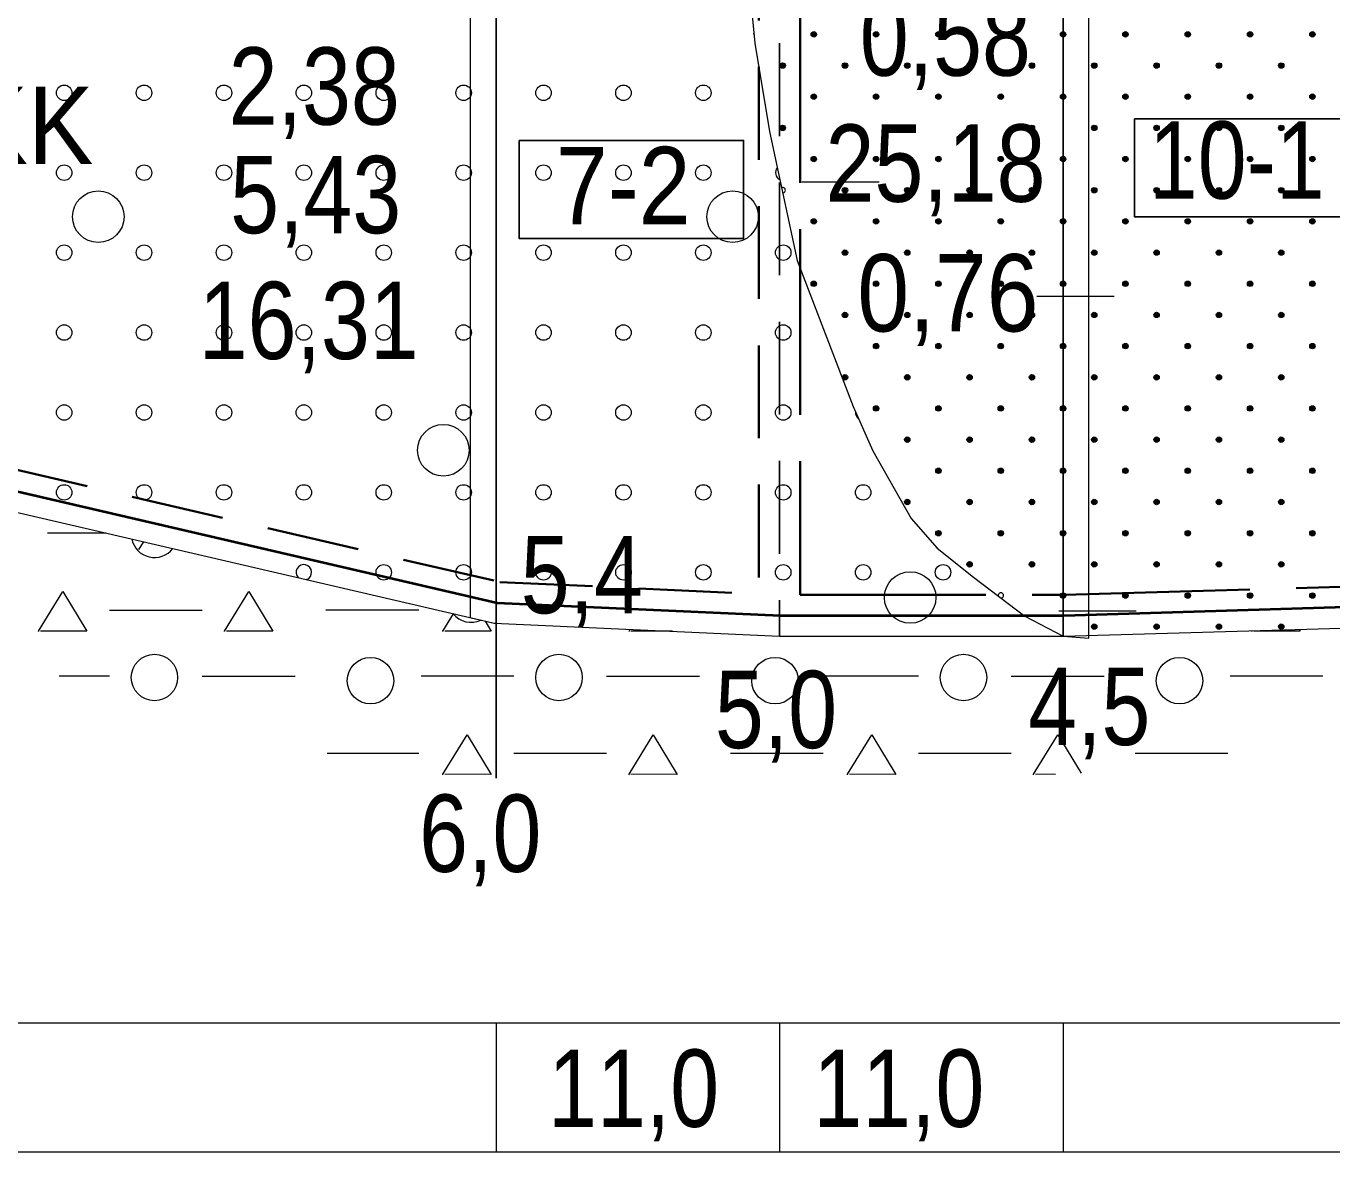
# Model space of a CAD drawing. Extents: x 640104 to 640970, y 6442278 to 6442689.
# Drawn here: x 640855 to 640905.7, y 6442488.9 to 6442532.6 of the extents above; entities that cross this region are included whole.
import ezdxf
from ezdxf.enums import TextEntityAlignment as Align

# ---------------------------------------------------------------- set-up
doc = ezdxf.new("R2010")
doc.units = 0
doc.header["$LTSCALE"] = 1.2
doc.linetypes.add('LONG_DASHED', pattern=[7.5, 6, -1.5])
doc.linetypes.add('MEDIUM_DASHED', pattern=[4.5, 3, -1.5])
for name, color, linetype, lineweight in [('30', 7, 'Continuous', 13), ('31', 7, 'Continuous', 13), ('32', 7, 'Continuous', 25), ('33', 7, 'Continuous', 13), ('35', 7, 'Continuous', 35), ('43', 7, 'Continuous', 13), ('45', 7, 'Continuous', 13), ('46', 7, 'Continuous', 13), ('47', 7, 'Continuous', 13)]:
    doc.layers.add(name, color=color, linetype=linetype, lineweight=lineweight)

msp = doc.modelspace()

# ---------------------------------------------------------------- hatches: boundary and pattern name
at = {"layer": '45'}
for points in [[(640885.671, 6442532.358, 1), (640885.523, 6442532.21, 1)], [(640888.089, 6442532.358, 1), (640887.941, 6442532.21, 1)], [(640890.508, 6442532.358, 1), (640890.359, 6442532.21, 1)], [(640892.926, 6442532.358, 1), (640892.777, 6442532.21, 1)], [(640895.344, 6442532.358, 1), (640895.196, 6442532.21, 1)], [(640897.763, 6442532.358, 1), (640897.614, 6442532.21, 1)], [(640900.181, 6442532.358, 1), (640900.032, 6442532.21, 1)], [(640902.599, 6442532.358, 1), (640902.451, 6442532.21, 1)], [(640905.017, 6442532.358, 1), (640904.869, 6442532.21, 1)], [(640884.462, 6442531.149, 1), (640884.313, 6442531, 1)], [(640886.88, 6442531.149, 1), (640886.732, 6442531, 1)], [(640889.299, 6442531.149, 1), (640889.15, 6442531, 1)], [(640891.717, 6442531.149, 1), (640891.568, 6442531, 1)], [(640894.135, 6442531.149, 1), (640893.987, 6442531, 1)], [(640896.553, 6442531.149, 1), (640896.405, 6442531, 1)], [(640898.972, 6442531.149, 1), (640898.823, 6442531, 1)], [(640901.39, 6442531.149, 1), (640901.242, 6442531, 1)], [(640903.808, 6442531.149, 1), (640903.66, 6442531, 1)], [(640885.671, 6442529.94, 1), (640885.523, 6442529.791, 1)], [(640888.089, 6442529.94, 1), (640887.941, 6442529.791, 1)], [(640890.508, 6442529.94, 1), (640890.359, 6442529.791, 1)], [(640892.926, 6442529.94, 1), (640892.777, 6442529.791, 1)], [(640895.344, 6442529.94, 1), (640895.196, 6442529.791, 1)], [(640897.763, 6442529.94, 1), (640897.614, 6442529.791, 1)], [(640900.181, 6442529.94, 1), (640900.032, 6442529.791, 1)], [(640902.599, 6442529.94, 1), (640902.451, 6442529.791, 1)], [(640905.017, 6442529.94, 1), (640904.869, 6442529.791, 1)], [(640884.462, 6442528.731, 1), (640884.313, 6442528.582, 1)], [(640886.88, 6442528.731, 1), (640886.732, 6442528.582, 1)], [(640889.299, 6442528.731, 1), (640889.15, 6442528.582, 1)], [(640891.717, 6442528.731, 1), (640891.568, 6442528.582, 1)], [(640894.135, 6442528.731, 1), (640893.987, 6442528.582, 1)], [(640896.553, 6442528.731, 1), (640896.405, 6442528.582, 1)], [(640898.972, 6442528.731, 1), (640898.823, 6442528.582, 1)], [(640901.39, 6442528.731, 1), (640901.242, 6442528.582, 1)], [(640903.808, 6442528.731, 1), (640903.66, 6442528.582, 1)], [(640885.671, 6442527.522, 1), (640885.523, 6442527.373, 1)], [(640888.089, 6442527.522, 1), (640887.941, 6442527.373, 1)], [(640890.508, 6442527.522, 1), (640890.359, 6442527.373, 1)], [(640892.926, 6442527.522, 1), (640892.777, 6442527.373, 1)], [(640895.344, 6442527.522, 1), (640895.196, 6442527.373, 1)], [(640897.763, 6442527.522, 1), (640897.614, 6442527.373, 1)], [(640900.181, 6442527.522, 1), (640900.032, 6442527.373, 1)], [(640902.599, 6442527.522, 1), (640902.451, 6442527.373, 1)], [(640905.017, 6442527.522, 1), (640904.869, 6442527.373, 1)], [(640886.88, 6442526.312, 1), (640886.732, 6442526.164, 1)], [(640889.299, 6442526.312, 1), (640889.15, 6442526.164, 1)], [(640891.717, 6442526.312, 1), (640891.568, 6442526.164, 1)], [(640894.135, 6442526.312, 1), (640893.987, 6442526.164, 1)], [(640896.553, 6442526.312, 1), (640896.405, 6442526.164, 1)], [(640898.972, 6442526.312, 1), (640898.823, 6442526.164, 1)], [(640901.39, 6442526.312, 1), (640901.242, 6442526.164, 1)], [(640903.808, 6442526.312, 1), (640903.66, 6442526.164, 1)], [(640885.671, 6442525.103, 1), (640885.523, 6442524.955, 1)], [(640888.089, 6442525.103, 1), (640887.941, 6442524.955, 1)], [(640890.508, 6442525.103, 1), (640890.359, 6442524.955, 1)], [(640892.926, 6442525.103, 1), (640892.777, 6442524.955, 1)], [(640895.344, 6442525.103, 1), (640895.196, 6442524.955, 1)], [(640897.763, 6442525.103, 1), (640897.614, 6442524.955, 1)], [(640900.181, 6442525.103, 1), (640900.032, 6442524.955, 1)], [(640902.599, 6442525.103, 1), (640902.451, 6442524.955, 1)], [(640905.017, 6442525.103, 1), (640904.869, 6442524.955, 1)], [(640886.88, 6442523.894, 1), (640886.732, 6442523.746, 1)], [(640889.299, 6442523.894, 1), (640889.15, 6442523.746, 1)], [(640891.717, 6442523.894, 1), (640891.568, 6442523.746, 1)], [(640894.135, 6442523.894, 1), (640893.987, 6442523.746, 1)], [(640896.553, 6442523.894, 1), (640896.405, 6442523.746, 1)], [(640898.972, 6442523.894, 1), (640898.823, 6442523.746, 1)], [(640901.39, 6442523.894, 1), (640901.242, 6442523.746, 1)], [(640903.808, 6442523.894, 1), (640903.66, 6442523.746, 1)], [(640885.671, 6442522.685, 1), (640885.523, 6442522.536, 1)], [(640888.089, 6442522.685, 1), (640887.941, 6442522.536, 1)], [(640890.508, 6442522.685, 1), (640890.359, 6442522.536, 1)], [(640892.926, 6442522.685, 1), (640892.777, 6442522.536, 1)], [(640895.344, 6442522.685, 1), (640895.196, 6442522.536, 1)], [(640897.763, 6442522.685, 1), (640897.614, 6442522.536, 1)], [(640900.181, 6442522.685, 1), (640900.032, 6442522.536, 1)], [(640902.599, 6442522.685, 1), (640902.451, 6442522.536, 1)], [(640905.017, 6442522.685, 1), (640904.869, 6442522.536, 1)], [(640886.88, 6442521.476, 1), (640886.732, 6442521.327, 1)], [(640889.299, 6442521.476, 1), (640889.15, 6442521.327, 1)], [(640891.717, 6442521.476, 1), (640891.568, 6442521.327, 1)], [(640894.135, 6442521.476, 1), (640893.987, 6442521.327, 1)], [(640896.553, 6442521.476, 1), (640896.405, 6442521.327, 1)], [(640898.972, 6442521.476, 1), (640898.823, 6442521.327, 1)], [(640901.39, 6442521.476, 1), (640901.242, 6442521.327, 1)], [(640903.808, 6442521.476, 1), (640903.66, 6442521.327, 1)], [(640888.089, 6442520.267, 1), (640887.941, 6442520.118, 1)], [(640890.508, 6442520.267, 1), (640890.359, 6442520.118, 1)], [(640892.926, 6442520.267, 1), (640892.777, 6442520.118, 1)], [(640895.344, 6442520.267, 1), (640895.196, 6442520.118, 1)], [(640897.763, 6442520.267, 1), (640897.614, 6442520.118, 1)], [(640900.181, 6442520.267, 1), (640900.032, 6442520.118, 1)], [(640902.599, 6442520.267, 1), (640902.451, 6442520.118, 1)], [(640905.017, 6442520.267, 1), (640904.869, 6442520.118, 1)], [(640886.88, 6442519.057, 1), (640886.732, 6442518.909, 1)], [(640889.299, 6442519.057, 1), (640889.15, 6442518.909, 1)], [(640891.717, 6442519.057, 1), (640891.568, 6442518.909, 1)], [(640894.135, 6442519.057, 1), (640893.987, 6442518.909, 1)], [(640896.553, 6442519.057, 1), (640896.405, 6442518.909, 1)], [(640898.972, 6442519.057, 1), (640898.823, 6442518.909, 1)], [(640901.39, 6442519.057, 1), (640901.242, 6442518.909, 1)], [(640903.808, 6442519.057, 1), (640903.66, 6442518.909, 1)], [(640888.089, 6442517.848, 1), (640887.941, 6442517.7, 1)], [(640890.508, 6442517.848, 1), (640890.359, 6442517.7, 1)], [(640892.926, 6442517.848, 1), (640892.777, 6442517.7, 1)], [(640895.344, 6442517.848, 1), (640895.196, 6442517.7, 1)], [(640897.763, 6442517.848, 1), (640897.614, 6442517.7, 1)], [(640900.181, 6442517.848, 1), (640900.032, 6442517.7, 1)], [(640902.599, 6442517.848, 1), (640902.451, 6442517.7, 1)], [(640905.017, 6442517.848, 1), (640904.869, 6442517.7, 1)], [(640889.299, 6442516.639, 1), (640889.15, 6442516.491, 1)], [(640891.717, 6442516.639, 1), (640891.568, 6442516.491, 1)], [(640894.135, 6442516.639, 1), (640893.987, 6442516.491, 1)], [(640896.553, 6442516.639, 1), (640896.405, 6442516.491, 1)], [(640898.972, 6442516.639, 1), (640898.823, 6442516.491, 1)], [(640901.39, 6442516.639, 1), (640901.242, 6442516.491, 1)], [(640903.808, 6442516.639, 1), (640903.66, 6442516.491, 1)], [(640890.508, 6442515.43, 1), (640890.359, 6442515.282, 1)], [(640892.926, 6442515.43, 1), (640892.777, 6442515.282, 1)], [(640895.344, 6442515.43, 1), (640895.196, 6442515.282, 1)], [(640897.763, 6442515.43, 1), (640897.614, 6442515.282, 1)], [(640900.181, 6442515.43, 1), (640900.032, 6442515.282, 1)], [(640902.599, 6442515.43, 1), (640902.451, 6442515.282, 1)], [(640905.017, 6442515.43, 1), (640904.869, 6442515.282, 1)], [(640889.299, 6442514.221, 1), (640889.15, 6442514.072, 1)], [(640891.717, 6442514.221, 1), (640891.568, 6442514.072, 1)], [(640894.135, 6442514.221, 1), (640893.987, 6442514.072, 1)], [(640896.553, 6442514.221, 1), (640896.405, 6442514.072, 1)], [(640898.972, 6442514.221, 1), (640898.823, 6442514.072, 1)], [(640901.39, 6442514.221, 1), (640901.242, 6442514.072, 1)], [(640903.808, 6442514.221, 1), (640903.66, 6442514.072, 1)], [(640890.508, 6442513.012, 1), (640890.359, 6442512.863, 1)], [(640892.926, 6442513.012, 1), (640892.777, 6442512.863, 1)], [(640895.344, 6442513.012, 1), (640895.196, 6442512.863, 1)], [(640897.763, 6442513.012, 1), (640897.614, 6442512.863, 1)], [(640900.181, 6442513.012, 1), (640900.032, 6442512.863, 1)], [(640902.599, 6442513.012, 1), (640902.451, 6442512.863, 1)], [(640905.017, 6442513.012, 1), (640904.869, 6442512.863, 1)], [(640891.717, 6442511.803, 1), (640891.568, 6442511.654, 1)], [(640894.135, 6442511.803, 1), (640893.987, 6442511.654, 1)], [(640896.553, 6442511.803, 1), (640896.405, 6442511.654, 1)], [(640898.972, 6442511.803, 1), (640898.823, 6442511.654, 1)], [(640901.39, 6442511.803, 1), (640901.242, 6442511.654, 1)], [(640903.808, 6442511.803, 1), (640903.66, 6442511.654, 1)], [(640895.344, 6442510.593, 1), (640895.196, 6442510.445, 1)], [(640897.763, 6442510.593, 1), (640897.614, 6442510.445, 1)], [(640900.181, 6442510.593, 1), (640900.032, 6442510.445, 1)], [(640902.599, 6442510.593, 1), (640902.451, 6442510.445, 1)], [(640905.017, 6442510.593, 1), (640904.869, 6442510.445, 1)], [(640896.553, 6442509.384, 1), (640896.405, 6442509.236, 1)], [(640898.972, 6442509.384, 1), (640898.823, 6442509.236, 1)], [(640901.39, 6442509.384, 1), (640901.242, 6442509.236, 1)], [(640903.808, 6442509.384, 1), (640903.66, 6442509.236, 1)]]:
    msp.add_hatch(color=256, dxfattribs=at).paths.add_polyline_path(points)

# ---------------------------------------------------------------- linework, layer by layer
at = {"layer": '30'}
for p, q in [((640524.54, 6442493.94), (640955.05, 6442493.94)), ((640873.27, 6442493.94), (640873.27, 6442488.94)), ((640884.27, 6442493.94), (640884.27, 6442488.94)), ((640895.27, 6442493.94), (640895.27, 6442488.94)), ((640524.54, 6442488.94), (640955.05, 6442488.94))]:
    msp.add_line(p, q, dxfattribs=at)
at = {"layer": '31'}
for points in [[(640553.71, 6442558.56), (640570.07, 6442558.94), (640649.85, 6442563.98), (640763.79, 6442536.22), (640808.67, 6442524.48), (640822.17, 6442520.94), (640837.77, 6442517.67), (640873.2, 6442509.45), (640884.27, 6442508.94), (640895.27, 6442508.94), (640947.47, 6442510.44), (640955.05, 6442510.44)], [(640879.76, 6442556.13), (640880.17, 6442555.04), (640880.81, 6442552.82), (640881.98, 6442546.26), (640882.74, 6442537.89), (640883.31, 6442531.94), (640883.88, 6442528.51), (640884.95, 6442523.51), (640887.12, 6442517.85), (640887.89, 6442516.13), (640889.37, 6442513.51), (640890.38, 6442512.35), (640891.79, 6442511.23), (640893.79, 6442509.72), (640895.27, 6442508.94)]]:
    msp.add_lwpolyline(points, dxfattribs=at)
at = {"layer": '32'}
for p, q in [((640873.27, 6442563.44), (640873.27, 6442503.44)), ((640895.27, 6442553.94), (640895.27, 6442508.94))]:
    msp.add_line(p, q, dxfattribs=at)
at = {"layer": '32', "linetype": 'MEDIUM_DASHED'}
msp.add_line((640884.27, 6442558.94), (640884.27, 6442508.94), dxfattribs=at)
at = {"layer": '33'}
for points in [[(640896.27, 6442548.59), (640895.37, 6442548.86), (640895.27, 6442548.86), (640895.27, 6442508.94), (640896.27, 6442508.87), (640896.27, 6442508.94)], [(640872.27, 6442538.44), (640872.27, 6442509.66), (640873.2, 6442509.45), (640873.27, 6442509.45), (640873.27, 6442538.44)]]:
    msp.add_lwpolyline(points, close=True, dxfattribs=at)
at = {"layer": '33', "lineweight": 25}
for points in [[(640898.04, 6442529.01), (640906.75, 6442529.01), (640906.75, 6442525.21), (640898.04, 6442525.21)], [(640874.16, 6442528.17), (640882.87, 6442528.17), (640882.87, 6442524.37), (640874.16, 6442524.37)]]:
    msp.add_lwpolyline(points, close=True, dxfattribs=at)
at = {"layer": '35', "linetype": 'LONG_DASHED'}
msp.add_line((640885.07, 6442551.73), (640885.07, 6442510.54), dxfattribs=at)
at = {"layer": '35', "linetype": 'MEDIUM_DASHED'}
msp.add_line((640883.47, 6442536.42), (640883.47, 6442510.58), dxfattribs=at)
msp.add_lwpolyline([(640823.77, 6442522.24), (640838.11, 6442519.23), (640873.42, 6442511.04), (640883.47, 6442510.58)], dxfattribs=at)
at = {"layer": '35', "lineweight": 40}
msp.add_lwpolyline([(640822.97, 6442521.59), (640837.94, 6442518.45), (640873.31, 6442510.24), (640884.29, 6442509.74), (640895.3, 6442509.74), (640946.67, 6442511.32)], dxfattribs=at)
at = {"layer": '35', "linetype": 'LONG_DASHED'}
msp.add_lwpolyline([(640885.07, 6442510.54), (640895.32, 6442510.54), (640945.87, 6442512.06)], dxfattribs=at)
at = {"layer": '43'}
for centre in [(640856.511, 6442530.018), (640859.611, 6442530.018), (640862.711, 6442530.018), (640865.811, 6442530.018), (640868.911, 6442530.018), (640872.011, 6442530.018), (640875.111, 6442530.018), (640878.211, 6442530.018), (640881.311, 6442530.018), (640856.511, 6442526.918), (640859.611, 6442526.918), (640862.711, 6442526.918), (640865.811, 6442526.918), (640868.911, 6442526.918), (640872.011, 6442526.918), (640875.111, 6442526.918), (640878.211, 6442526.918), (640881.311, 6442526.918), (640856.511, 6442523.818), (640859.611, 6442523.818), (640862.711, 6442523.818), (640865.811, 6442523.818), (640868.911, 6442523.818), (640872.011, 6442523.818), (640875.111, 6442523.818), (640878.211, 6442523.818), (640881.311, 6442523.818), (640884.411, 6442523.818), (640856.511, 6442520.718), (640859.611, 6442520.718), (640862.711, 6442520.718), (640865.811, 6442520.718), (640868.911, 6442520.718), (640872.011, 6442520.718), (640875.111, 6442520.718), (640878.211, 6442520.718), (640881.311, 6442520.718), (640884.411, 6442520.718), (640856.511, 6442517.618), (640859.611, 6442517.618), (640862.711, 6442517.618), (640865.811, 6442517.618), (640868.911, 6442517.618), (640872.011, 6442517.618), (640875.111, 6442517.618), (640878.211, 6442517.618), (640881.311, 6442517.618), (640884.411, 6442517.618), (640856.511, 6442514.518), (640859.611, 6442514.518), (640862.711, 6442514.518), (640865.811, 6442514.518), (640868.911, 6442514.518), (640872.011, 6442514.518), (640875.111, 6442514.518), (640878.211, 6442514.518), (640881.311, 6442514.518), (640884.411, 6442514.518), (640887.511, 6442514.518), (640868.911, 6442511.418), (640872.011, 6442511.418), (640875.111, 6442511.418), (640878.211, 6442511.418), (640881.311, 6442511.418), (640884.411, 6442511.418), (640887.511, 6442511.418), (640890.611, 6442511.418)]:
    msp.add_circle(centre, 0.3, dxfattribs=at)
for centre, start, end in [((640884.411, 6442526.918), 140.7659, 243.5192), ((640887.511, 6442517.618), 173.8824, 234.2968), ((640865.811, 6442511.418), 290.4586, 223.403)]:
    msp.add_arc(centre, 0.3, start, end, dxfattribs=at)
at = {"layer": '45'}
for centre in [(640885.597, 6442532.284), (640888.015, 6442532.284), (640890.433, 6442532.284), (640892.852, 6442532.284), (640895.27, 6442532.284), (640897.688, 6442532.284), (640900.107, 6442532.284), (640902.525, 6442532.284), (640904.943, 6442532.284), (640884.388, 6442531.075), (640886.806, 6442531.075), (640889.224, 6442531.075), (640891.643, 6442531.075), (640894.061, 6442531.075), (640896.479, 6442531.075), (640898.897, 6442531.075), (640901.316, 6442531.075), (640903.734, 6442531.075), (640885.597, 6442529.866), (640888.015, 6442529.866), (640890.433, 6442529.866), (640892.852, 6442529.866), (640895.27, 6442529.866), (640897.688, 6442529.866), (640900.107, 6442529.866), (640902.525, 6442529.866), (640904.943, 6442529.866), (640884.388, 6442528.656), (640886.806, 6442528.656), (640889.224, 6442528.656), (640891.643, 6442528.656), (640894.061, 6442528.656), (640896.479, 6442528.656), (640898.897, 6442528.656), (640901.316, 6442528.656), (640903.734, 6442528.656), (640885.597, 6442527.447), (640888.015, 6442527.447), (640890.433, 6442527.447), (640892.852, 6442527.447), (640895.27, 6442527.447), (640897.688, 6442527.447), (640900.107, 6442527.447), (640902.525, 6442527.447), (640904.943, 6442527.447), (640886.806, 6442526.238), (640889.224, 6442526.238), (640891.643, 6442526.238), (640894.061, 6442526.238), (640896.479, 6442526.238), (640898.897, 6442526.238), (640901.316, 6442526.238), (640903.734, 6442526.238), (640885.597, 6442525.029), (640888.015, 6442525.029), (640890.433, 6442525.029), (640892.852, 6442525.029), (640895.27, 6442525.029), (640897.688, 6442525.029), (640900.107, 6442525.029), (640902.525, 6442525.029), (640904.943, 6442525.029), (640886.806, 6442523.82), (640889.224, 6442523.82), (640891.643, 6442523.82), (640894.061, 6442523.82), (640896.479, 6442523.82), (640898.897, 6442523.82), (640901.316, 6442523.82), (640903.734, 6442523.82), (640885.597, 6442522.611), (640888.015, 6442522.611), (640890.433, 6442522.611), (640892.852, 6442522.611), (640895.27, 6442522.611), (640897.688, 6442522.611), (640900.107, 6442522.611), (640902.525, 6442522.611), (640904.943, 6442522.611), (640886.806, 6442521.402), (640889.224, 6442521.402), (640891.643, 6442521.402), (640894.061, 6442521.402), (640896.479, 6442521.402), (640898.897, 6442521.402), (640901.316, 6442521.402), (640903.734, 6442521.402), (640888.015, 6442520.192), (640890.433, 6442520.192), (640892.852, 6442520.192), (640895.27, 6442520.192), (640897.688, 6442520.192), (640900.107, 6442520.192), (640902.525, 6442520.192), (640904.943, 6442520.192), (640886.806, 6442518.983), (640889.224, 6442518.983), (640891.643, 6442518.983), (640894.061, 6442518.983), (640896.479, 6442518.983), (640898.897, 6442518.983), (640901.316, 6442518.983), (640903.734, 6442518.983), (640888.015, 6442517.774), (640890.433, 6442517.774), (640892.852, 6442517.774), (640895.27, 6442517.774), (640897.688, 6442517.774), (640900.107, 6442517.774), (640902.525, 6442517.774), (640904.943, 6442517.774), (640889.224, 6442516.565), (640891.643, 6442516.565), (640894.061, 6442516.565), (640896.479, 6442516.565), (640898.897, 6442516.565), (640901.316, 6442516.565), (640903.734, 6442516.565), (640890.433, 6442515.356), (640892.852, 6442515.356), (640895.27, 6442515.356), (640897.688, 6442515.356), (640900.107, 6442515.356), (640902.525, 6442515.356), (640904.943, 6442515.356), (640889.224, 6442514.147), (640891.643, 6442514.147), (640894.061, 6442514.147), (640896.479, 6442514.147), (640898.897, 6442514.147), (640901.316, 6442514.147), (640903.734, 6442514.147), (640890.433, 6442512.937), (640892.852, 6442512.937), (640895.27, 6442512.937), (640897.688, 6442512.937), (640900.107, 6442512.937), (640902.525, 6442512.937), (640904.943, 6442512.937), (640891.643, 6442511.728), (640894.061, 6442511.728), (640896.479, 6442511.728), (640898.897, 6442511.728), (640901.316, 6442511.728), (640903.734, 6442511.728), (640895.27, 6442510.519), (640897.688, 6442510.519), (640900.107, 6442510.519), (640902.525, 6442510.519), (640904.943, 6442510.519), (640896.479, 6442509.31), (640898.897, 6442509.31), (640901.316, 6442509.31), (640903.734, 6442509.31)]:
    msp.add_circle(centre, 0.105, dxfattribs=at)
for centre, start, end in [((640883.178, 6442532.284), 342.2983, 28.5929), ((640884.388, 6442526.238), 270.6596, 113.6255), ((640892.852, 6442510.519), 277.7439, 187.9089)]:
    msp.add_arc(centre, 0.105, start, end, dxfattribs=at)
at = {"layer": '46'}
for p, q in [((640858.13, 6442512.94), (640855.87, 6442512.94)), ((640859.41, 6442512.3), (640859.6, 6442512.6)), ((640861.87, 6442509.94), (640858.27, 6442509.94)), ((640870.27, 6442509.95), (640866.67, 6442509.95)), ((640880.11, 6442509.13), (640878.5, 6442509.14)), ((640858.27, 6442507.39), (640856.32, 6442507.39)), ((640865.47, 6442507.38), (640861.87, 6442507.38)), ((640873.96, 6442507.39), (640870.36, 6442507.39)), ((640881.16, 6442507.38), (640877.56, 6442507.38)), ((640889.66, 6442507.39), (640886.06, 6442507.39)), ((640896.86, 6442507.38), (640893.26, 6442507.38)), ((640905.35, 6442507.39), (640901.75, 6442507.39)), ((640870.27, 6442504.39), (640866.72, 6442504.39)), ((640877.56, 6442504.39), (640873.96, 6442504.39)), ((640885.96, 6442504.39), (640882.36, 6442504.39)), ((640893.26, 6442504.39), (640889.66, 6442504.39)), ((640901.66, 6442504.39), (640898.06, 6442504.39)), ((640894.97, 6442503.58), (640894.2, 6442503.59))]:
    msp.add_line(p, q, dxfattribs=at)
for points in [[(640855.5, 6442509.12), (640855.51, 6442509.14), (640856.46, 6442510.67), (640857.39, 6442509.13), (640855.59, 6442509.14)], [(640862.73, 6442509.12), (640862.73, 6442509.14), (640863.68, 6442510.67), (640864.61, 6442509.13), (640862.81, 6442509.14)], [(640871.2, 6442509.12), (640871.2, 6442509.14), (640871.62, 6442509.81)], [(640872.84, 6442509.53), (640873.08, 6442509.13), (640871.28, 6442509.14)], [(640878.42, 6442509.12), (640878.43, 6442509.14), (640878.47, 6442509.21)], [(640902.59, 6442509.12), (640902.59, 6442509.14), (640902.6, 6442509.15)], [(640904.43, 6442509.2), (640904.47, 6442509.13), (640902.67, 6442509.14)], [(640871.2, 6442503.56), (640871.2, 6442503.59), (640872.15, 6442505.12), (640873.08, 6442503.58), (640871.28, 6442503.59)], [(640878.42, 6442503.56), (640878.43, 6442503.59), (640879.37, 6442505.12), (640880.3, 6442503.58), (640878.5, 6442503.59)], [(640886.9, 6442503.56), (640886.9, 6442503.59), (640887.85, 6442505.12), (640888.78, 6442503.58), (640886.98, 6442503.59)], [(640894.12, 6442503.56), (640894.12, 6442503.59), (640895.07, 6442505.12), (640895.97, 6442503.63)]]:
    msp.add_lwpolyline(points, dxfattribs=at)
for centre in [(640860.015, 6442507.338), (640868.397, 6442507.216), (640875.71, 6442507.338), (640884.092, 6442507.216), (640891.405, 6442507.338), (640899.787, 6442507.216)]:
    msp.add_circle(centre, 0.9, dxfattribs=at)
for centre, start, end in [((640860.015, 6442512.893), 191.5895, 322.2721), ((640872.3, 6442510.38), 218.5771, 295.2844)]:
    msp.add_arc(centre, 0.9, start, end, dxfattribs=at)
at = {"layer": '47'}
for p, q in [((640885.13, 6442526.57), (640888.13, 6442526.57)), ((640894.25, 6442522.13), (640897.25, 6442522.13)), ((640895.11, 6442509.93), (640898.11, 6442509.93))]:
    msp.add_line(p, q, dxfattribs=at)
for centre in [(640857.835, 6442525.211), (640882.447, 6442525.211), (640871.224, 6442516.153), (640889.338, 6442510.443)]:
    msp.add_circle(centre, 1, dxfattribs=at)

# ---------------------------------------------------------------- texts
at = {"layer": '30', "width": 0.85}
for p in [(640878.605, 6442489.91), (640888.895, 6442489.91)]:
    msp.add_text('11,0', height=3, dxfattribs=at).set_placement(p, align=Align.CENTER)
at = {"layer": '32', "width": 0.85}
for s, p in [('5,4', (640876.595, 6442509.83)), ('5,0', (640884.13, 6442504.6)), ('4,5', (640896.285, 6442504.72)), ('6,0', (640872.655, 6442499.8))]:
    msp.add_text(s, height=3, dxfattribs=at).set_placement(p, align=Align.CENTER)
at = {"layer": '33'}
for s, width, p in [('0,58', 0.85, (640890.7, 6442530.68)), ('2,38', 0.85, (640866.215, 6442528.78)), ('25,18', 0.85, (640890.32, 6442525.79)), ('10-1', 0.85, (640902.01, 6442525.91)), ('7-2', 0.9, (640878.205, 6442524.92)), ('5,43', 0.85, (640866.27, 6442524.57)), ('0,76', 0.9, (640890.8, 6442520.76)), ('16,31', 0.85, (640866, 6442519.69))]:
    msp.add_text(s, height=3, dxfattribs=dict(at, width=width)).set_placement(p, align=Align.CENTER)
at = {"layer": '35', "width": 0.95}
msp.add_text('3. PLOKK', height=3, dxfattribs=at).set_placement((640849.175, 6442527.25), align=Align.CENTER)

doc.saveas('drawing.dxf')
